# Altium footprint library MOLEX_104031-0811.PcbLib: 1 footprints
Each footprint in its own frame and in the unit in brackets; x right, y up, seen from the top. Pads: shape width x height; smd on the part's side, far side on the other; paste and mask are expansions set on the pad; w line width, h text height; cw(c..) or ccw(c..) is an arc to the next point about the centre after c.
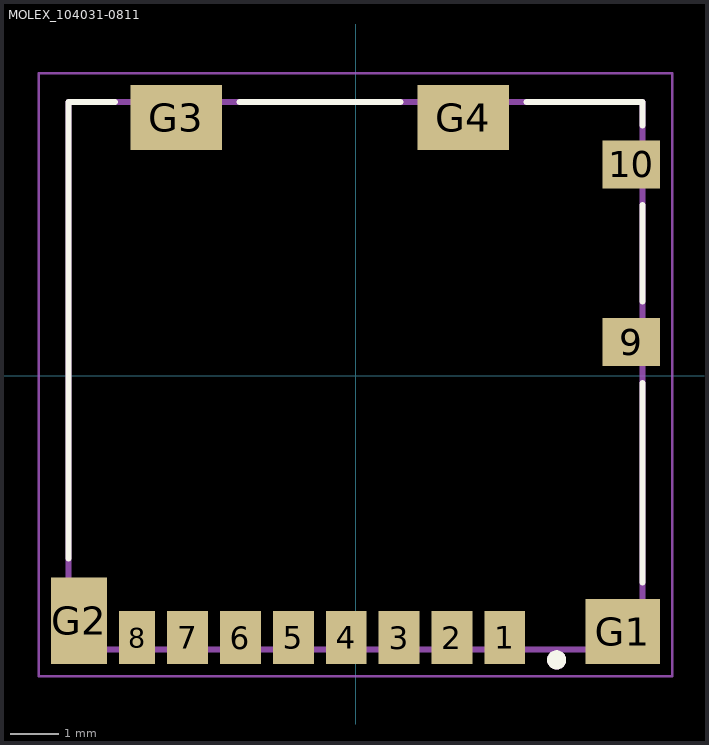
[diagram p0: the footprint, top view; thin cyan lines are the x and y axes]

## MOLEX_104031-0811 [mm]
height 1.57
pads (14):
  rect 0.85x1.1 smd: 1(3.105,-5.45) 2(2.005,-5.45) 3(0.905,-5.45) 4(-0.195,-5.45) 5(-1.295,-5.45) 6(-2.395,-5.45) 7(-3.495,-5.45)
  rect 0.75x1.1 smd: 8(-4.545,-5.45)
  rect 1.2x1 smd: 9(5.74,0.7) 10(5.74,4.4)
  rect 1.55x1.35 smd: G1(5.565,-5.325)
  rect 1.17x1.8 smd: G2(-5.755,-5.1)
  rect 1.9x1.35 smd: G3(-3.73,5.375) G4(2.24,5.375)
Top Overlay:
  circle w0.2: c4.184,-5.912 r0.1
  lines w0.127: -5.975,-3.806 -5.975,5.7 -5.003,5.7 ; -2.413,5.7 0.939,5.7 ; 3.556,5.7 5.975,5.7 5.975,5.211 ; 5.975,-4.3 5.975,-0.15 ; 5.975,1.55 5.975,3.55
Assembly Top:
  circle w0.2: c4.184,-5.912 r0.1
  lines w0.127: -5.975,-5.7 -5.975,5.7 5.975,5.7 5.975,-5.7 -5.975,-5.7
Courtyard Top:
  lines w0.05: -6.59,-6.25 -6.59,6.3 6.59,6.3 6.59,-6.25 -6.59,-6.25
3D body "1040310811.stp": height 1.45, standoff 0, extent -5.975,-5.842 5.975,5.558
